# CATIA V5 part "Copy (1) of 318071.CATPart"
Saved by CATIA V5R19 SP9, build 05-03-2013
Part number: Copy (1) of 318071
Source: Unknown
Bounding box of the stored display mesh (mm): x -136 to 26.779, y 110.238 to 128.64, z 475.082 to 497.334
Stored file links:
  D:\16-SIL\kale oto\R19_V2\Copy (1) of 318071.CATPart
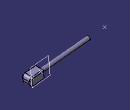
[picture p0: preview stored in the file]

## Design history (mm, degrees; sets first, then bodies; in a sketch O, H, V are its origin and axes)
Set1
  Point1: stored without definition
  Point2 "Point.3": stored without definition
  Point3 "Point.4": stored without definition
  Plane1: type OffsetPt, RefPlane face of Solid1, RefPoint Point2
Body1 "241\\236\\235\\MANIFOLD_SOLID_BREP #159996" (main body)
  Solid1: solid without history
